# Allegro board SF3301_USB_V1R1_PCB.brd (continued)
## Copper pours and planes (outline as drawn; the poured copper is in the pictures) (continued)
P12V_FLT on ART02 (solid shape): outline of 708 points within 1.36,15.26 31.59,51.83
VBUS_5V on TOP (solid shape): 59.65,12.33 59.65,11.57 59.45,10.02 59.55,9.17 60.04,7.51 59.91,7.25 58.77,6.87 58.51,7 57.88,9.41 57.11,10.18 57.11,12.21 57.37,12.46 59.53,12.46
VBUS_5V on TOP (solid shape): 64.86,12.72 64.86,12.31 64.66,12.31 63.77,11.42 63.77,10.79 63.59,10.61 63.31,10.61 63.19,10.73 63.19,12.56 63.46,12.84 64.73,12.84
VBUS_5V on BOTTOM (solid shape): 60.16,11.06 62.88,11.06 63.19,11.37 63.19,11.95 63.31,12.08 63.67,12.08 63.8,11.95 63.8,10.61 62.98,9.79 58.64,9.79 57.11,11.32 57.11,12.33 57.24,12.46 58.77,12.46
VCC_1V8 on TOP (solid shape): 56.86,91.46 56.86,89.96 55.18,88.28 53.94,88.28 53.81,88.41 53.81,89.55 54.02,89.75 55.11,89.75 55.9,90.54 55.9,91.51 55.97,91.58 56.73,91.58
VCC_1V8 on BOTTOM (solid shape): outline of 159 points within 37.68,74.56 58.97,90.44
VCC_3V3 on TOP (solid shape): 65.83,16.37 65.83,16.27 65.8,16.25 65.07,16.25 65.01,16.2 65.01,16.04 65.09,15.97 65.78,15.97 65.85,15.89 65.85,15.69 65.93,15.61 66.13,15.61 66.26,15.48 66.26,14.75 66.13,14.62 65.62,14.62 64.73,15.51 62.07,15.51 61.94,15.64 61.94,16.02 62.07,16.14 64.43,16.14 64.73,16.45 65.75,16.45
VCC_3V3 on TOP (solid shape): outline of 679 points within 56.64,17.16 93.69,95.49
VCC_3V3 on BOTTOM (solid shape): 74.83,97.61 74.83,96.73 75.76,95.8 77.66,95.8 77.79,95.67 77.79,94.4 77.54,94.15 75.56,94.15 74.72,93.31 74.72,92.17 73.55,91 69.13,91 69,91.13 69,92.37 68.75,92.62 68.75,97.58 69.1,97.93 74.51,97.93
VCC_3V3 on BOTTOM (solid shape): 56.1,90.08 56.1,89.3 56.99,88.41 58.18,88.41 58.42,88.17 58.42,86.29 58.33,86.2 57.95,86.2 57.68,86.47 57.67,86.48 57.52,86.63 56.23,86.63 56.1,86.5 56.1,85.44 56.2,85.33 57.39,85.33 57.52,85.21 57.52,84.67 57.39,84.55 55.95,84.55 55.67,84.83 55.67,86.08 55.67,86.99 56.12,87.44 56.12,88.36 56.07,88.41 56.07,88.48 55.9,88.66 55.54,88.66 55.24,88.97 55.24,90.03 55.41,90.21 55.97,90.21
VCC_3V3 on BOTTOM (solid shape): outline of 215 points within 61.99,7.36 84.8,18.96
VCC_5V0 on BOTTOM (solid shape): 65.65,96.13 65.65,95.14 66.17,94.61 66.17,94.56 66.23,94.56 66.89,93.89 66.89,90.72 66.98,90.63 73.74,90.63 75.38,92.27 75.38,93.13 75.68,93.44 77.64,93.44 78.22,92.85 78.83,92.85 79.09,92.6 79.09,92.34 79.34,92.09 83.4,92.09 84.29,91.2 84.29,87.52 84.04,87.26 81.24,87.26 79.59,88.91 79.59,88.92 78.07,88.92 77.69,88.92 76.16,88.92 76.16,88.91 75.66,88.41 74.26,88.41 72.99,89.68 66.34,89.68 65.85,90.16 65.85,91.91 65.85,91.91 65.85,93.34 65.83,93.34 64.38,94.78 64.38,96 64.61,96.23 65.55,96.23
VCC_P5V0 on TOP (solid shape): 66.13,100.73 66.13,98.95 64.48,97.3 63.21,97.3 62.96,97.55 62.96,98.31 65.12,100.47 65.12,100.73 65.24,100.85 66,100.85
VCC_P5V0 on BOTTOM (solid shape): 66.39,98.19 66.39,97.01 66.36,96.98 63.78,96.98 63.52,97.25 64.43,97.25 64.43,97.7 63.87,97.7 63.87,97.25 63.52,97.25 63.36,97.4 63.36,98.26 63.72,98.62 65.95,98.62
0 on TOP (solid shape): 57.88,29.99 59.91,29.99 60.04,29.86 60.04,29.1 59.91,28.97 53.05,28.97 52.92,29.1 52.92,30.37 53.3,30.75 57.11,30.75
0 on TOP (solid shape): 65.04,77.73 65.04,77.18 64.98,77.09 64.87,77.11 63.09,78.89 63.07,79 63.16,79.06 63.71,79.06
0 on TOP (solid shape): 70.07,73.57 70.13,73.66 70.24,73.64 70.58,73.3 70.58,63.47 70.51,63.37 70.4,63.39 70.07,63.73
0 on TOP (solid shape): 72.56,73.67 72.62,73.77 72.73,73.75 73.24,73.23 73.24,62.68 73.18,62.59 73.07,62.61 72.56,63.12
0 on TOP (solid shape): 71.9,73.79 71.9,63.03 71.83,62.94 71.72,62.96 71.24,63.45 71.24,73.58 69.03,75.79 69.01,75.9 69.1,75.96 69.73,75.96
0 on TOP (solid shape): 17.61,51.7 17.65,51.69 17.66,51.65 17.66,50.38 14.59,47.31 14.57,47.29 14.46,47.26 14.39,47.35 14.39,48.21 16.68,50.5 16.68,51.65 16.69,51.69 16.73,51.7
0 on TOP (solid shape): 14.88,42.39 14.94,42.48 15.05,42.46 15.89,41.62 17.87,41.62 20.49,39 20.49,37.35 21.35,36.49 21.38,36.4 21.33,36.33 21.3,36.3 21.25,36.26 18.05,36.26 14.88,39.44
0 on TOP (solid shape): 9.68,83.83 9.78,83.79 9.9,83.79 9.92,83.78 9.94,83.77 10.12,83.58 10.12,83.04 10.1,83.01 10.1,81.61 10.12,81.59 10.12,81.51 10.1,81.49 10.1,80.09 10.32,80.09 10.33,80.08 10.33,78.17 10.31,78.14 10.28,78.12 9.24,78.12 9.11,78.25 9.11,83.58 9.36,83.84 9.67,83.84
0 on TOP (solid shape): 63.69,79.89 63.71,79.78 63.62,79.72 54.54,79.72 54.45,79.78 54.46,79.89 54.42,80.46 53.85,80.49 53.84,80.48 50.75,80.48 50.25,79.98 50.14,79.96 50.08,80.05 50.08,80.14 51.16,81.22 62.36,81.22
0 on TOP (solid shape): 56.22,85.49 56.33,85.51 56.39,85.42 56.39,85.11 57.37,84.14 57.85,84.14 58.06,84.22 58.16,84.41 58.33,84.57 58.51,84.41 58.52,84.3 58.7,84.14 62.15,84.14 62.7,84.69 62.74,84.71 62.77,84.69 63.33,84.14 63.35,84.03 63.26,83.96 54.93,83.96 54.84,84.03 54.86,84.14
0 on TOP (solid shape): 67.33,81.28 67.36,81.27 67.38,81.23 67.38,80.56 67.39,80.56 67.42,80.54 67.44,80.51 67.44,80.38 67.45,80.38 67.53,80.35 67.55,80.27 67.81,79.86 68.29,79.95 68.41,79.97 68.47,79.88 68.47,79.04 67.83,78.41 67.72,78.38 67.66,78.48 67.66,79.1 66.28,80.47 65.64,81.11 65.62,81.22 65.71,81.28
0 on TOP (solid shape): 75.65,19.62 75.75,19.56 75.73,19.45 75.64,19.36 74.22,19.36 72.03,17.17 71.94,17.15 71.86,17.21 71.7,17.39 71.47,17.47 71.39,17.5 71.36,17.57 71.36,18.52 71.24,18.52 71.2,18.53 71.19,18.57 71.19,18.58 70.47,18.58 70.47,18.57 70.46,18.53 70.42,18.52 70.3,18.52 70.3,18.11 70.24,18.05 70.16,18.02 70.08,18.07 70.07,18.11 70.08,18.14 70.09,18.55 69.74,18.77 69.11,18.77 69.07,18.78 69.06,18.84 69.06,19.49 69.06,19.51 69.08,19.59 69.16,19.62
0 on TOP (solid shape): outline of 432 points within 12.97,48.63 27.27,98.42
0 on TOP (solid shape): outline of 4500 points within 0.51,0.51 94.49,113.84
0 on TOP (solid shape): outline of 8946 points within 14.1,32.35 64.79,99.46
0 on BOTTOM (solid shape): 54.7,16.4 54.7,13.48 53.69,12.46 52.16,12.46 51.91,12.72 51.91,15.69 53.13,16.91 54.19,16.91
0 on BOTTOM (solid shape): 58,70.75 58,70.35 57.92,70.27 52.5,70.27 52.11,70.65 52.11,70.87 52.12,70.87 57.88,70.87
0 on BOTTOM (solid shape): 64.05,66.06 64.05,65.45 63.92,65.32 60.98,65.32 60.85,65.45 60.85,66.18 60.92,66.26 63.85,66.26
0 on BOTTOM (solid shape): 42.56,63.84 42.58,63.84 42.6,63.82 42.87,63.56 42.87,63.28 42.79,63.2 37.72,63.2 37.61,63.31 37.61,63.71 37.73,63.84
0 on BOTTOM (solid shape): 57.93,70.73 57.93,70.42 57.88,70.37 52.54,70.37 52.21,70.7 52.21,70.72 52.23,70.76 52.26,70.77 57.88,70.77
0 on BOTTOM (solid shape): 42.82,69.3 42.84,69.3 42.85,69.29 43.02,69.12 43.02,68.97 42.73,68.68 42.71,68.67 42.69,68.67 37.74,68.67 37.63,68.77 37.63,69.2 37.73,69.3
0 on BOTTOM (solid shape): 37.81,52.97 39.08,52.97 39.59,52.47 39.59,49.67 36.41,49.67 35.78,50.31 35.78,50.69 34.76,51.7 34.76,52.56 35.29,53.09 35.89,53.09 35.91,53.1 37.18,53.1 37.3,53.23 37.56,53.23
0 on BOTTOM (solid shape): 29.68,49.8 29.68,47.39 29.43,47.13 22.7,47.13 22.44,47.39 22.44,49.04 26.13,49.04 26.13,49.67 25.11,49.67 25.11,49.04 22.44,49.04 22.44,51.07 22.7,51.32 28.16,51.32
0 on BOTTOM (solid shape): 34.51,59.45 34.51,56.78 34,56.28 30.7,56.28 30.19,56.78 30.19,57.93 33.87,57.93 33.87,58.44 33.24,58.44 33.24,57.93 32.6,57.93 32.6,58.44 31.84,58.44 31.84,57.93 30.19,57.93 30.19,59.45 30.32,59.58 34.38,59.58
0 on BOTTOM (solid shape): 47.08,53.1 49.88,53.1 49.88,50.31 49.37,49.8 45.81,49.8 45.05,50.56 45.05,52.34 49.49,52.34 49.49,52.59 49.24,52.59 49.24,52.34 45.05,52.34 45.05,52.85 45.18,52.97 46.32,52.97 46.57,53.23 46.95,53.23
0 on BOTTOM (solid shape): 55.44,67.61 55.49,67.6 55.55,67.57 55.76,67.57 55.77,67.56 55.77,67.4 55.77,66.46 55.76,66.46 54.79,66.46 54.78,66.46 54.78,66.56 54.8,66.58 54.8,67.08 55.03,67.31 55.03,67.56 55.04,67.57 55.34,67.57 55.4,67.6
0 on BOTTOM (solid shape): 75.02,84.32 75.06,84.3 75.07,84.27 75.07,83.49 74.82,83.23 74.82,82.96 74.44,82.58 73.94,82.58 73.9,82.59 73.89,82.63 73.89,83.16 73.87,83.29 73.81,83.41 73.8,83.42 73.8,83.54 74.57,84.32
0 on BOTTOM (solid shape): 57.04,67.61 57.09,67.6 57.15,67.57 57.88,67.57 57.95,67.5 57.95,66.65 57.89,66.58 57.01,66.58 56.98,66.6 56.96,66.63 56.96,67.19 56.86,67.19 56.83,67.21 56.81,67.24 56.81,67.56 56.82,67.57 56.94,67.57 57,67.6
0 on BOTTOM (solid shape): 43.65,64.55 50.15,64.55 50.19,64.54 50.21,64.5 50.21,64.19 50.2,64.16 50.17,64.14 50.16,64.14 50.13,64.14 43.78,64.14 43.52,64.4 43.47,64.43 43.44,64.48 43.02,64.91 37.84,64.91 37.8,64.92 37.79,64.96 37.79,65.37 37.85,65.44 42.76,65.44
0 on BOTTOM (solid shape): 50.86,60.7 50.89,60.72 50.93,60.7 51.15,60.49 57.88,60.49 57.9,60.47 57.9,60.13 57.89,60.1 57.85,60.08 52.8,60.08 52.71,59.99 52.67,59.97 52.63,59.99 52.54,60.08 37.79,60.08 37.75,60.1 37.74,60.13 37.74,60.54 37.8,60.61 50.76,60.61
0 on BOTTOM (solid shape): 48.44,57.31 48.48,57.3 48.49,57.26 48.49,56.86 48.48,56.83 48.44,56.81 48.26,56.81 48.26,56.51 48.2,56.42 48.09,56.44 47.82,56.71 38.45,56.71 38.19,56.45 37.81,56.45 37.76,56.5 37.76,56.98 37.78,57.02 37.81,57.03 38.34,57.03 38.34,57.29 38.37,57.31
0 on BOTTOM (solid shape): 32.22,73.68 32.22,72.53 32.48,72.28 32.48,72.02 32.22,71.77 32.22,70.5 32.48,70.25 32.48,69.99 32.22,69.74 32.22,68.47 32.48,68.21 32.48,68.09 32.35,67.96 31.33,67.96 30.95,68.34 29.56,68.34 29.43,68.47 29.43,70.37 31.84,70.37 31.84,70.63 31.59,70.63 31.59,70.37 29.43,70.37 29.43,70.88 31.84,70.88 31.84,71.39 31.59,71.39 31.59,70.88 29.43,70.88 29.43,71.64 31.84,71.64 31.84,71.9 31.59,71.9 31.59,71.64 29.43,71.64 29.43,73.55 29.56,73.68 30.83,73.68 30.95,73.8 32.1,73.8
0 on BOTTOM (solid shape): 57.77,85.94 57.77,85.88 57.85,85.88 57.89,85.86 57.9,85.83 57.9,85.77 58.61,85.77 58.65,85.75 58.66,85.71 58.66,83.06 58.99,82.73 58.99,82.64 58.96,82.59 58.91,82.6 57.44,84.07 57.42,84.18 57.51,84.24 57.52,84.24 57.83,84.55 57.83,85.33 57.52,85.64 56.46,85.64 56.42,85.65 56.4,85.69 56.4,86.27 56.42,86.31 56.46,86.32 57.39,86.32
0 on BOTTOM (solid shape): 26.43,37.66 26.47,37.64 26.48,37.61 26.48,37.58 27.5,37.58 28.2,36.89 28.2,34.15 28.15,34.06 28.05,34.06 27.87,34.1 27.69,34.07 27.66,34.06 27.63,34.08 27.61,34.12 27.61,36.24 27.29,36.24 26.72,36.81 26.25,36.81 26.22,36.82 26.2,36.86 26.2,37.53 26.22,37.57 26.25,37.58 26.28,37.58 26.28,37.61 26.29,37.64 26.33,37.66
0 on BOTTOM (solid shape): 70.35,12.12 70.4,12.21 70.5,12.21 70.62,12.16 70.76,12.16 70.83,12.13 70.87,12.06 70.87,12.05 71.15,12.05 71.18,12.04 71.2,12 71.2,10.8 70.14,9.74 70.03,9.72 69.97,9.81 69.97,10.52 69.82,10.52 69.78,10.53 69.76,10.57 69.76,10.58 69.78,10.62 69.82,10.63 70.35,10.63
0 on BOTTOM (solid shape): 53.7,97.44 53.76,97.45 53.79,97.41 53.79,96.51 55.62,96.51 55.62,96.89 55.63,96.93 55.67,96.94 55.7,96.94 56.76,95.88 56.76,95.47 56.74,95.43 56.71,95.42 56.45,95.42 56.45,93.87 56.44,93.83 56.4,93.82 56.05,93.82 56.01,93.83 56,93.87 56,94.4 54.45,94.4 54.41,94.42 54.4,94.45 54.4,95.15 53.71,95.83 53.71,96.12 53.56,96.12 53.52,96.13 53.51,96.17 53.51,97.15 53.52,97.16 53.57,97.24 53.6,97.33 53.6,97.35
0 on BOTTOM (solid shape): 52.69,58.99 52.73,59.01 52.77,58.99 52.8,58.96 57.88,58.96 57.91,58.95 57.93,58.91 57.93,58.61 57.91,58.57 57.88,58.56 52.8,58.56 52.59,58.35 52.55,58.33 52.52,58.35 52.38,58.48 49.65,58.48 49.42,58.24 49.36,58.16 49.25,58.17 49.08,58.24 48.9,58.21 48.81,58.22 48.76,58.3 48.5,58.56 37.79,58.56 37.75,58.57 37.74,58.61 37.74,58.84 37.75,58.88 37.79,58.89 52.59,58.89
0 on BOTTOM (solid shape): 58.5,93.16 58.53,93.14 58.55,93.11 58.55,92.06 59.04,92.06 59.14,92 59.12,91.89 59.09,91.86 58.55,91.86 58.55,91.71 58.53,91.67 58.5,91.66 58.21,91.66 58.17,91.67 58.16,91.71 58.16,92.55 56.96,92.55 56.96,89.11 56.9,89.02 56.79,89.04 56.4,89.42 56.4,90.21 56.25,90.36 56.25,90.62 55.06,90.62 55.06,90.51 54.99,90.41 54.88,90.44 54.73,90.59 54.73,91.8 54.58,91.8 54.54,91.81 54.52,91.85 54.52,92.1 54.4,92.23 54.4,92.78 54.41,92.81 54.45,92.83 56,92.83 56,93.11 56.01,93.14 56.05,93.16
0 on BOTTOM (solid shape): 78.83,74.69 78.83,71.77 78.07,71.01 75.91,71.01 75.66,70.75 75.66,70.12 75.91,69.87 76.04,69.87 76.7,69.21 78.58,69.21 80.2,67.58 80.2,66.18 79.19,65.17 74.26,65.17 73.22,66.21 76.77,66.21 76.77,67.66 75.81,67.66 75.81,66.21 73.22,66.21 70.2,69.23 67.2,69.23 66.44,69.99 66.44,70.68 69.64,70.68 69.64,72.3 68.57,72.3 68.57,70.68 66.44,70.68 66.44,73.73 66.56,73.85 67.07,73.85 67.22,74.01 75.48,74.01 75.48,74.44 74.69,74.44 74.69,74.01 74.34,74.01 74.34,74.46 73.52,74.46 73.52,74.01 73.27,74.01 73.27,74.46 72.38,74.46 72.38,74.01 72.05,74.01 72.05,74.49 71.24,74.49 71.24,74.01 67.22,74.01 67.25,74.03 70.86,74.03 70.86,74.51 70.04,74.51 70.04,74.03 69.79,74.03 69.79,74.54 68.95,74.54 68.95,74.03 68.72,74.03 68.72,74.51 67.68,74.51 67.68,74.03 67.25,74.03 67.27,74.06 67.27,74.82 67.4,74.95 78.58,74.95
0 on BOTTOM (solid shape): 88.89,85.16 88.89,84.7 87.39,83.2 87.39,83.17 87.24,83.02 80.2,83.02 80.17,83.04 80.15,83.07 80.15,83.48 78.78,83.48 78.78,82.16 78.81,82.16 78.84,82.14 78.86,82.11 78.86,82.01 78.85,81.98 78.83,81.96 78.78,81.93 78.78,81.8 78.77,81.77 78.73,81.75 78.71,81.75 78.67,81.77 78.65,81.8 78.65,82.02 78.63,82.02 78.59,82.03 78.58,82.07 78.58,82.41 77.36,82.41 77.36,82.07 77.34,82.03 77.31,82.02 77.28,82.02 77.28,81.96 77.27,81.92 77.23,81.91 76.39,81.91 76.39,81.84 76.38,81.81 76.34,81.79 76.27,81.79 76.27,81.3 76.25,81.26 76.22,81.25 75.4,81.25 75.16,81.49 75.13,81.5 75.12,81.52 75.12,81.55 75.13,81.57 75.67,82.11 76.32,82.11 76.32,82.17 76.33,82.21 76.37,82.22 76.44,82.22 76.44,82.8 77.2,83.56 78.63,83.56 78.63,84.65 79.59,85.61 88.43,85.61
0 on BOTTOM (solid shape): 44.59,70.27 44.63,70.25 44.64,70.21 44.64,70.14 45.46,70.14 45.46,70.21 45.47,70.25 45.51,70.27 46.12,70.27 46.15,70.25 46.17,70.21 46.17,70.14 46.98,70.14 46.98,70.21 47,70.25 47.03,70.27 47.77,70.27 47.8,70.25 47.82,70.21 47.82,70.14 48.63,70.14 48.63,70.21 48.65,70.25 48.68,70.27 49.42,70.27 49.45,70.25 49.47,70.21 49.47,70.14 50.28,70.14 50.35,70.22 50.46,70.19 50.64,70.01 51.4,70.01 52.29,69.12 57.83,69.12 57.86,69.11 57.88,69.07 57.88,68.89 57.84,68.86 57.83,68.85 57.81,68.84 52.42,68.84 51.65,69.61 50.38,69.61 50.29,69.51 50.26,69.5 50.22,69.51 50.13,69.61 43.65,69.61 43.29,69.96 43.27,70.07 43.37,70.14 44.06,70.14 44.06,70.21 44.07,70.25 44.11,70.27
0 on BOTTOM (solid shape): 56.25,31.89 56.29,31.87 56.3,31.84 56.3,31.66 57.62,31.66 57.62,31.68 57.64,31.72 57.67,31.73 57.77,31.73 57.81,31.72 57.83,31.68 57.83,31.66 57.98,31.66 58.01,31.64 58.03,31.61 58.03,31.07 58.01,31.04 57.98,31.02 57.93,31.02 57.35,30.55 57.71,29.9 57.77,29.8 57.71,29.71 57.51,29.58 57.39,29.39 57.38,29.38 56.22,28.22 56.11,28.2 56.05,28.29 56.05,30.94 55.42,31.57 55.4,31.6 55.41,31.63 55.42,31.66 55.43,31.66 55.43,31.84 55.44,31.87 55.48,31.89
0 on BOTTOM (solid shape): 68.09,58.61 68.09,54.5 65.8,52.21 57.22,52.21 55.79,50.79 52.77,50.79 52.74,50.8 52.73,50.81 52.72,50.84 52.72,52.59 53.3,53.18 54.83,53.18 55.26,53.61 55.26,56.15 55.16,56.25 62.58,56.25 62.58,56.61 62.02,56.61 62.02,56.25 61.69,56.25 61.69,56.63 61.05,56.63 61.05,56.25 55.16,56.25 54.96,56.45 50.77,56.45 50.64,56.33 50.61,56.31 50.58,56.31 50.55,56.31 50.52,56.32 50.5,56.34 50.48,56.36 50.47,56.39 50.47,56.41 50.47,56.81 50.02,56.81 49.65,57.18 49.63,57.2 49.59,57.23 49.54,57.26 49.49,57.27 49.44,57.28 49.39,57.28 49.33,57.28 49.27,57.26 49.24,57.27 49.22,57.28 49.2,57.3 49.18,57.33 49.18,57.55 49.35,57.73 49.37,57.73 49.39,57.73 49.41,57.71 49.42,57.68 49.71,57.39 52.38,57.39 52.48,57.47 52.5,57.47 52.52,57.46 52.8,57.18 60.47,57.18 60.5,57.18 60.51,57.16 60.52,57.09 63.11,57.09 63.12,57.16 63.13,57.18 63.16,57.18 63.53,57.18 64.15,57.8 64.15,58.92 64.46,59.22 67.48,59.22
0 on BOTTOM (solid shape): 44.59,62.77 44.63,62.76 44.64,62.72 44.64,62.59 45.46,62.59 45.46,62.72 45.47,62.76 45.51,62.77 46.24,62.77 46.28,62.76 46.29,62.72 46.29,62.59 47.11,62.59 47.11,62.72 47.12,62.76 47.16,62.77 47.77,62.77 47.8,62.76 47.82,62.72 47.82,62.62 48.63,62.62 48.63,62.72 48.65,62.76 48.68,62.77 49.29,62.77 49.33,62.76 49.34,62.72 49.34,62.62 50.03,62.62 50.06,62.6 50.08,62.57 50.08,62.44 50.38,62.14 57.88,62.14 57.9,62.12 57.9,61.78 57.89,61.75 57.85,61.73 51.15,61.73 51.12,61.7 51.08,61.69 51.05,61.7 50.89,61.86 49.75,61.86 49.24,62.37 48.73,62.37 48.35,61.99 48.1,61.99 47.72,62.37 47.21,62.37 46.83,61.99 46.45,61.99 46.07,62.37 45.56,62.37 45.18,61.99 44.92,61.99 44.54,62.37 43.91,62.37 43.27,61.73 37.76,61.73 37.73,61.75 37.71,61.78 37.71,62.09 37.73,62.12 37.76,62.14 43.02,62.14 43.32,62.44 43.32,62.57 43.37,62.62 43.93,62.62 43.93,62.72 43.95,62.76 43.98,62.77
0 on BOTTOM (solid shape): 63.09,98.67 63.19,98.61 63.16,98.5 63.06,98.39 63.02,98.39 63.02,98.31 63.01,98.28 62.97,98.26 62.91,98.26 62.91,97.45 62.97,97.45 63.01,97.43 63.02,97.4 63.02,97.32 63.03,97.32 63.06,97.29 63.06,97.27 63.66,96.67 63.66,96.67 63.69,96.66 63.7,96.64 63.7,96.61 63.69,96.59 63.34,96.24 62.68,96.24 62.68,94.03 62.88,94.03 63.38,93.53 63.4,93.42 63.31,93.36 63.12,93.36 62.66,93.82 62.53,93.82 62.49,93.83 62.47,93.87 62.47,95.23 61.37,95.23 61.34,95.25 61.34,95.26 61.16,95.5 60.87,95.57 60.79,95.59 60.76,95.67 60.76,95.67 59.8,95.67 59.76,95.69 59.74,95.72 59.74,95.82 59.76,95.86 59.8,95.87 59.86,95.87 59.86,96.69 59.8,96.69 59.76,96.7 59.74,96.74 59.74,96.81 59.76,96.85 59.8,96.87 59.96,96.87 61.76,98.67
0 on BOTTOM (solid shape): 55.49,82.24 55.55,82.34 55.66,82.32 56.4,81.57 57.42,81.57 57.46,81.56 57.47,81.52 57.47,79.85 57.46,79.81 57.42,79.8 56.01,79.8 56.01,78.81 55.51,78.31 55.51,78.3 55.48,78.27 54.36,78.27 54.36,77.19 54.4,77.15 54.41,77.08 54.4,76.97 54.41,76.85 54.4,76.76 54.32,76.72 53.69,76.72 53.61,76.76 53.58,76.83 53.56,77.02 53.46,77.19 53.44,77.28 53.49,77.35 53.67,77.51 53.74,77.74 53.77,77.81 53.84,77.84 53.9,77.84 53.9,79.63 53.94,79.71 54.03,79.73 54.47,79.91 54.48,80.39 54.47,80.4 54.47,80.56 54.56,80.65 55.46,80.65 55.46,81.74 55.49,81.76
0 on BOTTOM (solid shape): 50.64,84.98 50.77,84.93 52.03,84.93 52.16,84.98 52.28,84.93 52.36,84.85 52.36,84.42 52.69,84.09 52.69,83.48 52.68,83.44 52.64,83.43 51.55,83.43 51.55,82.9 51.54,82.86 51.5,82.85 51.48,82.85 51.48,81.52 51.64,81.52 51.68,81.51 51.69,81.47 51.69,79.43 51.63,79.34 51.52,79.36 51.45,79.43 51.45,79.44 51.24,79.76 50.86,79.79 50.77,79.81 50.73,79.89 50.73,81.47 50.74,81.51 50.78,81.52 51.07,81.52 51.07,82.85 51.04,82.85 51.01,82.86 50.99,82.9 50.99,83.43 49.77,83.43 49.77,82.9 49.76,82.86 49.72,82.85 49.7,82.85 49.7,81.5 49.68,81.46 49.65,81.45 49.56,81.45 49.52,81.46 49.51,81.5 49.51,82.02 49.47,82.06 49.47,82.85 49.44,82.85 49.41,82.86 49.39,82.9 49.39,83 49.41,83.03 49.44,83.05 49.47,83.05 49.47,83.63 49.55,83.71 49.55,84.09 50.38,84.93 50.5,84.93
0 on BOTTOM (solid shape): outline of 98 points within 41.8,65.8 53.89,68.59
0 on BOTTOM (solid shape): outline of 97 points within 61.84,71.82 69.46,87.92
0 on BOTTOM (solid shape): 85.04,82.11 85.08,82.09 85.1,82.06 85.1,79.94 86.98,79.94 87.02,79.92 87.04,79.89 87.04,76.34 86.91,76.22 86.36,76.22 86.33,76.23 86.31,76.27 85.18,76.27 84.18,77.27 84.18,77.31 84.18,77.32 83.78,77.92 83.39,77.32 83.39,77.31 83.39,76.94 83.77,76.57 83.79,76.46 83.69,76.39 80.86,76.39 80.83,76.41 80.81,76.44 80.81,76.48 79.65,77.64 78.16,77.64 78,77.79 77.98,77.9 78.08,77.97 78.79,77.97 78.79,79.03 78.81,79.07 78.85,79.09 79.11,79.09 79.11,80.46 77.79,80.46 77.79,80.43 77.78,80.4 77.74,80.38 77.64,80.38 77.6,80.4 77.59,80.43 77.59,80.46 76.27,80.46 76.27,80.04 76.25,80 76.22,79.99 75.65,79.99 75.56,80.03 75.55,80.13 75.58,80.28 75.55,80.44 75.56,80.54 75.64,80.58 76.66,80.58 76.67,80.6 77.26,80.6 77.28,80.57 78.65,80.57 78.65,80.79 78.67,80.82 78.71,80.84 78.73,80.84 78.77,80.82 78.78,80.79 78.78,80.63 80.15,80.63 80.15,81.96 80.13,81.96 80.09,81.97 80.08,82.01 80.08,82.06 80.09,82.09 80.13,82.11
0 on BOTTOM (solid shape): 77.92,88.61 77.95,88.6 77.97,88.56 77.97,88.31 79.57,88.31 79.62,88.27 79.61,88.22 79.58,88.19 79.58,87.05 78.8,86.27 78.69,86.25 78.63,86.34 78.63,86.4 77.26,86.4 77.22,86.42 77.21,86.45 77.21,86.46 77.05,86.46 77.02,86.48 77,86.52 77,86.64 76.98,86.67 76.97,86.68 76.45,87.05 76.14,86.49 76.14,86.48 76.14,84.73 75.85,84.45 75.59,84.45 75.5,84.5 75.5,84.61 75.53,85.06 75.14,85.28 75.07,85.31 75.04,85.39 75.05,85.42 75.09,85.44 75.58,85.84 75.14,86.3 75.07,86.33 75.04,86.4 73.8,86.4 73.77,86.42 73.75,86.45 73.75,86.55 73.77,86.59 73.8,86.6 73.84,86.6 73.84,87.89 73.86,87.92 73.89,87.94 73.93,87.94 73.97,87.92 73.98,87.89 73.98,87.82 75.68,87.82 75.68,87.89 75.7,87.92 75.73,87.94 75.81,87.94 75.81,88.13 75.98,88.3 76.01,88.32 76.04,88.31 76.06,88.31 77.79,88.31 77.79,88.56 77.81,88.6 77.84,88.61
0 on BOTTOM (solid shape): outline of 224 points within 33.97,81.25 61.3,99.79
0 on BOTTOM (solid shape): outline of 332 points within 57.49,11.37 64.95,20.41
0 on BOTTOM (solid shape): outline of 396 points within 37.63,71.32 49.04,80.18
0 on BOTTOM (solid shape): outline of 204 points within 48.87,71.28 73.4,95.89
0 on BOTTOM (solid shape): outline of 5673 points within 0.51,0.51 94.49,113.84
0 on ART02 (solid shape): outline of 43839 points within 0.51,0.51 94.49,113.84
0 on ART03 (solid shape): outline of 49739 points within 0.51,0.51 94.49,113.84
6314_ISEN on TOP (solid shape): 84.01,76.01 84.01,71.64 83.73,71.36 79.34,71.36 79.16,71.54 79.16,75.89 79.42,76.14 83.89,76.14
6314_ISEN on BOTTOM (solid shape): 84.17,75.83 84.17,75.2 84.55,74.82 86.07,74.82 86.32,74.56 86.32,71.9 87.21,71.01 88.36,71.01 88.74,70.63 88.74,67.71 87.98,66.94 81.37,66.94 78.96,69.36 78.96,70.5 79.34,70.88 79.34,75.96 79.47,76.09 83.91,76.09
BTC_VDD on TOP (solid shape): 73.75,45.1 73.75,43.2 73.7,43.15 37.73,43.15 37.56,43.32 37.56,45.86 39.08,47.39 62.88,47.39 64.63,49.14 69.71,49.14
BTC_VDD on TOP (solid shape): 32.1,109.87 32.1,99.2 35.65,95.65 35.65,79.9 35.4,79.64 33.11,79.64 30.57,77.1 30.57,56.66 25.87,51.96 16.22,51.96 16.09,52.09 16.09,52.21 16.35,52.47 16.35,55.29 20.11,55.29 20.11,55.23 20.11,55.17 20.13,55.12 20.15,55.06 20.19,55.01 20.22,54.96 20.27,54.92 20.31,54.89 20.37,54.86 20.42,54.84 20.48,54.83 20.54,54.83 20.6,54.83 20.66,54.84 20.71,54.86 20.76,54.89 20.81,54.92 20.86,54.96 20.89,55.01 20.92,55.06 20.95,55.12 20.96,55.17 20.97,55.23 20.97,55.29 20.96,55.35 20.95,55.41 20.92,55.46 20.89,55.51 20.86,55.56 20.81,55.6 20.76,55.63 20.71,55.66 20.66,55.68 20.6,55.69 20.54,55.69 20.48,55.69 20.42,55.68 20.37,55.66 20.31,55.63 20.27,55.6 20.22,55.56 20.19,55.51 20.15,55.46 20.13,55.41 20.11,55.35 20.11,55.29 16.35,55.29 16.35,59.32 16.6,59.58 22.57,59.58 23.08,60.09 23.08,65.67 23.59,66.18 23.59,79.01 27.52,82.95 27.52,94 22.95,98.57 22.95,109.74 23.21,110 31.97,110
BTC_VDD on BOTTOM (solid shape): 52.42,58.12 52.42,57.74 52.29,57.62 49.81,57.62 49.65,57.78 49.65,58.15 49.75,58.25 52.29,58.25
BTC_VDD on BOTTOM (solid shape): 48.48,74 48.48,73.62 48.35,73.49 47.84,73.49 47.72,73.36 47.21,73.36 47.08,73.49 46.45,73.49 46.19,73.24 46.19,72.98 46.83,72.35 46.83,72.09 46.7,71.97 45.97,71.97 45.92,71.99 45.3,72.6 45.13,72.6 45.04,72.61 44.96,72.6 44.8,72.6 44.29,72.09 43.27,72.09 42.76,72.6 41.93,72.6 41.84,72.61 41.76,72.6 40.33,72.6 40.24,72.61 40.16,72.6 39.21,72.6 39.08,72.73 39.08,73.24 39.21,73.36 42.64,73.36 43.27,72.73 43.53,72.73 44.29,73.49 45.18,73.49 45.81,74.13 48.35,74.13
BTC_VDD on BOTTOM (solid shape): outline of 679 points within 16.09,40.27 74.64,110.25
BTC_VDD on ART02 (solid shape): outline of 3412 points within 31.33,53.36 54.96,78.5
LTC_VDD on BOTTOM (solid shape): outline of 243 points within 50.38,56.91 89.12,74.16
LTC_VDD on ART03 (solid shape): outline of 2036 points within 50.13,57.27 88.92,74.06
PSU_12V on TOP (solid shape): outline of 107 points within 39.72,11.57 57.37,18.68
PSU_12V on BOTTOM (solid shape): 85.44,39.39 85.44,37.35 79.59,31.51 79.59,26.81 73.5,20.72 61.56,20.72 59.27,18.43 59.27,15.13 54.96,10.81 50.64,10.81 47.91,13.54 40.41,13.54 39.72,14.24 39.72,16.28 51.41,16.28 51.41,12.65 52.11,11.95 54.07,11.95 55.46,13.35 55.46,17.29 55.21,17.54 52.67,17.54 51.41,16.28 39.72,16.28 39.72,17.92 40.48,18.68 56.73,18.68 60.29,22.24 71.85,22.24 77.05,27.45 77.05,33.04 83.66,39.64 85.18,39.64
RT8802A_PHASE1 on TOP (solid shape): 71.59,36.59 71.59,33.92 71.72,33.8 72.74,33.8 72.86,33.67 72.86,33.16 71.34,31.64 71.34,29.23 71.21,29.1 67.66,29.1 67.53,29.23 67.53,30.62 67.4,30.75 65.24,30.75 65.12,30.62 65.12,29.23 64.99,29.1 61.94,29.1 61.81,29.23 61.81,30.5 61.43,30.88 60.67,30.88 60.54,31 60.54,31.89 63.72,31.89 63.72,32.27 62.96,32.27 62.96,31.89 60.54,31.89 59.78,32.65 59.78,33.29 59.02,34.05 59.02,35.83 59.91,36.72 71.47,36.72
RT8802A_PHASE1 on BOTTOM (solid shape): 73.62,36.72 73.62,31.13 73.5,31 71.59,31 71.47,30.88 71.47,29.35 71.34,29.23 62.19,29.23 61.94,29.48 61.94,31.38 60.67,32.65 60.67,33.92 71.85,33.92 71.85,34.56 70.32,34.56 70.32,33.92 63.59,33.92 63.59,34.56 62.7,34.56 62.7,33.92 60.67,33.92 60.67,36.59 60.92,36.85 73.5,36.85
RT8802A_PHASE2 on TOP (solid shape): 22.06,110 22.06,99.71 21.94,99.58 20.92,99.58 20.79,99.46 20.79,98.31 20.67,98.19 19.65,98.19 18,96.54 18,88.15 17.87,88.03 11.14,88.03 10.63,88.53 10.63,92.98 10.12,93.49 10.12,98.57 14.57,103.01 14.57,109.87 14.82,110.12 21.94,110.12
RT8802A_PHASE2 on BOTTOM (solid shape): 22.06,110 22.06,98.31 21.94,98.19 18.25,98.19 18,97.93 18,86.76 17.87,86.63 13.43,86.63 12.41,87.65 10.25,87.65 10.12,87.77 10.12,88.92 13.55,88.92 13.55,89.55 13.05,89.55 13.05,88.92 10.12,88.92 10.12,90.95 16.47,90.95 16.47,91.33 15.84,91.33 15.84,90.95 15.33,90.95 15.33,91.33 14.7,91.33 14.7,90.95 10.12,90.95 10.12,91.58 10.25,91.71 11.9,91.71 12.03,91.84 12.03,92.09 16.47,92.09 16.47,92.47 15.84,92.47 15.84,92.09 15.46,92.09 15.46,92.47 14.7,92.47 14.7,92.09 12.03,92.09 12.03,93.23 11.78,93.49 10.25,93.49 10.12,93.61 10.12,96.66 16.47,96.66 16.47,97.04 15.84,97.04 15.84,96.66 14.32,96.66 14.32,97.04 13.68,97.04 13.68,96.66 10.12,96.66 10.12,99.33 10.38,99.58 11.52,99.58 13.55,101.62 18.51,101.62 18.51,102 17.36,102 17.36,101.62 13.55,101.62 14.57,102.63 14.57,106.7 18.51,106.7 18.51,107.2 17.36,107.2 17.36,106.7 14.57,106.7 14.57,109.74 14.95,110.12 21.94,110.12
RT8802A_PHASE3 on TOP (solid shape): 17.49,77.49 17.49,66.18 17.36,66.06 14.57,66.06 14.19,65.67 14.19,56.4 14.06,56.28 9.24,56.28 9.11,56.4 9.11,69.61 9.33,69.83 10.95,69.83 10.95,71.05 10.89,71.05 10.58,71.36 10.58,71.72 10.38,71.92 9.26,71.92 9.24,71.9 8.98,71.9 8.85,72.02 8.85,75.55 10.95,75.55 10.95,75.73 11.26,75.73 11.52,75.98 11.52,76.34 11.26,76.59 10.95,76.59 10.95,76.77 9.3,76.77 9.3,75.55 8.85,75.55 8.85,77.23 9.24,77.61 17.36,77.61
RT8802A_PHASE3 on BOTTOM (solid shape): 14.95,75.07 15.97,75.07 16.73,74.31 17.36,74.31 17.49,74.18 17.49,72.28 17.36,72.15 15.84,72.15 15.71,72.02 15.71,70.37 15.84,70.25 16.86,70.25 16.98,70.12 16.98,69.74 17.49,69.23 17.49,68.21 17.11,67.83 17.11,66.18 16.22,65.29 15.2,65.29 14.95,65.04 14.95,56.66 14.7,56.4 9.24,56.4 9.11,56.53 9.11,66.31 11.39,66.31 11.39,67.2 10.63,67.2 10.63,66.31 9.11,66.31 9.11,70.12 10.2,71.21 10.2,71.67 9.74,72.13 9.74,75.2 10,75.45 14.57,75.45
RT8802A_PHASE4 on TOP (solid shape): 51.27,36.34 51.27,32.78 51.4,32.65 52.54,32.65 52.67,32.53 52.67,31.64 51.78,30.75 51.78,28.84 51.65,28.72 47.84,28.72 47.72,28.84 47.72,30.5 47.59,30.62 47.56,30.62 47.56,30.63 46.35,30.63 46.35,30.62 46.32,30.62 46.19,30.5 46.19,29.35 46.07,29.23 42.13,29.23 42,29.35 42,30.62 41.87,30.75 40.1,30.75 39.97,30.88 39.97,33.8 46.7,33.8 46.7,34.69 46.19,34.69 46.19,33.8 45.68,33.8 45.68,34.69 45.3,34.69 45.3,33.8 40.99,33.8 40.99,34.56 40.6,34.56 40.6,33.8 39.97,33.8 39.97,36.34 40.1,36.46 51.15,36.46
RT8802A_PHASE4 on BOTTOM (solid shape): 51.02,36.46 51.02,30.37 50.13,29.48 40.73,29.48 40.6,29.61 40.6,30.75 37.94,33.42 37.94,33.8 40.22,33.8 40.22,33.92 47.21,33.92 47.21,34.56 46.19,34.56 46.19,33.92 40.22,33.92 40.22,34.56 39.21,34.56 39.21,33.8 37.94,33.8 37.94,36.46 38.19,36.72 50.76,36.72
N17034652 on BOTTOM (solid shape): 90.13,40.27 92.55,40.27 92.8,40.02 92.8,38.37 92.55,38.12 88.86,38.12 88.36,38.62 87.21,38.62 86.45,39.39 86.45,41.93 86.58,42.05 88.36,42.05
N17512182 on TOP (solid shape): 54.96,93.87 54.96,93.49 53.94,92.47 53.94,91.84 54.19,91.58 54.96,91.58 55.08,91.46 55.08,90.82 54.83,90.57 53.3,90.57 53.18,90.69 53.18,94 53.43,94.25 54.57,94.25
N17552651 on TOP (solid shape): 24.22,24.53 24.22,20.59 24.35,20.46 25.36,20.46 25.49,20.34 25.49,19.57 25.36,19.45 24.35,19.45 24.22,19.32 24.22,16.65 24.09,16.53 17.74,16.53 17.62,16.65 17.62,23 19.27,24.65 24.09,24.65
N17552651 on BOTTOM (solid shape): 23.84,23.89 23.84,16.65 23.71,16.53 18.38,16.53 18.25,16.65 18.25,23.89 18.38,24.02 23.71,24.02
N17581619 on BOTTOM (solid shape): 90.82,94.27 90.82,87.98 90.24,87.39 87.98,87.39 87.59,87.77 87.59,90.95 88.86,92.22 88.86,94.25 88.36,94.76 86.71,94.76 86.58,94.88 86.58,95.39 86.71,95.52 89.58,95.52

Small or netless copper shapes (teardrops, artwork), in the pictures only: 3 on TOP, 17 on BOTTOM

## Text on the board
BOTTOM: ARTWORK BOTTOM
Ref Des/Silkscreen Bottom: D | E | F | B | A | C | GND | 3V3 | CLKOUT | STX | SRX | ETX | ERX | FAN
User.Comments: SOLDMASK TOP | SOLDMASK BOTTOM
TOP: ARTWORK TOP
Ref Des/Silkscreen Top: 1 | A | AC | 23 | SF3301_USB_V1.1
ART02: ARTWORK LAYER02
ART03: ARTWORK LAYER03
DISPLAY_BOTTOM: PASTEMASK BOTTOM
DISPLAY_TOP: PASTEMASK TOP
